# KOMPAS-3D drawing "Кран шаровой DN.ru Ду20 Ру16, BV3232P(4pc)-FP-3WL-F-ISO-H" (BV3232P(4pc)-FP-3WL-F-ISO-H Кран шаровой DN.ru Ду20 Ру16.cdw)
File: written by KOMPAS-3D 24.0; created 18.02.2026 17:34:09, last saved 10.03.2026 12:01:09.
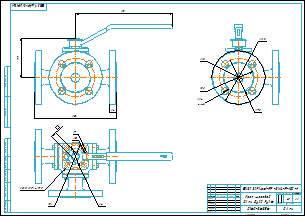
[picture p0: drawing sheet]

Document properties: Автор: R2D2; Форматы листов документа: A2; Полное имя файла: BV3232P(4pc)-FP-3WL-F-ISO-H Кран шаровой DN.ru Ду20 Ру16.m3d; Масса: 4.5; Наименование: Кран шаровой DN.ru Ду20 Ру16; Количество листов документа: 1; Примечание: D160-36356

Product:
- Part/product: Кран шаровой DN.ru Ду20 Ру16  | designation BV3232P(4pc)-FP-3WL-F-ISO-H
    Масса: 4.5
    Раздел спецификации: Прочие изделия
    Форматы листов документа: A2
    Примечание: D160-36356

Views: Вид 1, Спереди, Проекционный вид 2
Referenced files in E:\Работа\Зайцев\BV3232P(4pc)-FP-3WL-F-ISO-H Кран шаровой DN.ru Ду15-100 Ру16\DN20\: BV3232P(4pc)-FP-3WL-F-ISO-H Кран шаровой DN.ru Ду20 Ру16.m3d
Referenced files in E:\Работа\Зайцев\Для компаса\: чертеж DN.ru А3.cdt
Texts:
  BV3232P(4pc)-FP-3WL-F-ISO-H
  чертеж DN.ru А3.cdt
  Кран шаровой
  DN.ru Ду20 Ру16
  Кран шаровой DN.ru Ду20 Ру16
  BV3232P(4pc)-FP-3WL-F-ISO-H Кран шаровой DN.ru Ду20 Ру16
Dimensions and other numbers on the sheet: 0; 3; 2; 4; 160; 14; 77; 190; 105; 75; 58; 18; 4 отв.; 1:1; 1; 4,5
